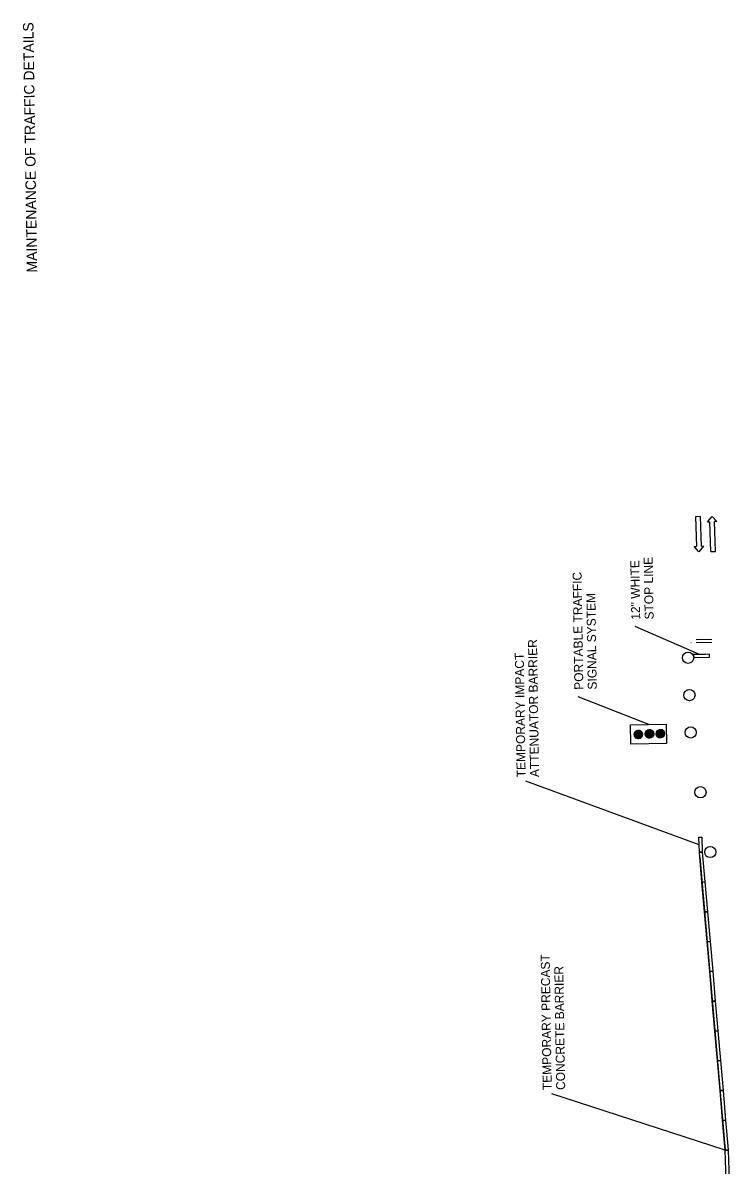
# Model space of a CAD drawing. Extents: x 1770269 to 1771406, y 724066 to 730989.
# Drawn here: x 1770350 to 1770823, y 724837 to 725601 of the extents above; entities that cross this region are included whole.
import ezdxf

# ---------------------------------------------------------------- set-up
doc = ezdxf.new("R2010")
doc.units = 0
for name, color, linetype in [('Default', 7, 'Continuous'), ('R_Border', 7, 'Continuous'), ('R_Border Notes', 7, 'Continuous'), ('R_Dimension', 7, 'Continuous'), ('R_MOT', 7, 'Continuous'), ('R_Striping', 7, 'Continuous'), ('T_Vehicle Path Rt', 7, 'Continuous')]:
    doc.layers.add(name, color=color, linetype=linetype)

msp = doc.modelspace()

# ---------------------------------------------------------------- linework, layer by layer
at = {"layer": 'Default'}
for p, q in [((1770797.34, 725186.19), (1770797.5, 725186.19)), ((1770762.37, 725121.93), (1770759.32, 725124.89)), ((1770762.19, 725121.92), (1770759.32, 725124.71)), ((1770762.53, 725121.94), (1770759.33, 725125.05)), ((1770762.01, 725121.93), (1770759.33, 725124.53)), ((1770762.69, 725121.97), (1770759.34, 725125.21)), ((1770761.81, 725121.95), (1770759.35, 725124.33)), ((1770762.84, 725122), (1770759.37, 725125.36)), ((1770762.98, 725122.03), (1770759.4, 725125.5)), ((1770761.59, 725121.99), (1770759.4, 725124.11)), ((1770763.11, 725122.08), (1770759.44, 725125.64)), ((1770761.34, 725122.05), (1770759.47, 725123.87)), ((1770763.24, 725122.12), (1770759.48, 725125.77)), ((1770763.37, 725122.18), (1770759.53, 725125.9)), ((1770763.49, 725122.23), (1770759.59, 725126.02)), ((1770761.05, 725122.16), (1770759.59, 725123.58)), ((1770763.61, 725122.3), (1770759.65, 725126.14)), ((1770763.72, 725122.36), (1770759.71, 725126.25)), ((1770763.82, 725122.43), (1770759.78, 725126.36)), ((1770760.66, 725122.36), (1770759.8, 725123.2)), ((1770763.93, 725122.51), (1770759.85, 725126.46)), ((1770764.03, 725122.59), (1770759.92, 725126.56)), ((1770764.12, 725122.67), (1770760, 725126.66)), ((1770764.21, 725122.75), (1770760.08, 725126.76)), ((1770764.3, 725122.84), (1770760.17, 725126.85)), ((1770764.38, 725122.94), (1770760.26, 725126.93)), ((1770764.46, 725123.03), (1770760.36, 725127.01)), ((1770764.54, 725123.14), (1770760.46, 725127.09)), ((1770764.61, 725123.24), (1770760.56, 725127.17)), ((1770764.67, 725123.35), (1770760.67, 725127.24)), ((1770764.74, 725123.46), (1770760.78, 725127.3)), ((1770764.79, 725123.58), (1770760.89, 725127.36)), ((1770764.85, 725123.7), (1770761.01, 725127.42)), ((1770764.9, 725123.83), (1770761.14, 725127.47)), ((1770764.94, 725123.96), (1770761.27, 725127.52)), ((1770764.98, 725124.1), (1770761.4, 725127.56)), ((1770765.01, 725124.24), (1770761.55, 725127.6)), ((1770765.04, 725124.39), (1770761.69, 725127.63)), ((1770765.05, 725124.55), (1770761.85, 725127.65)), ((1770765.06, 725124.71), (1770762.02, 725127.67)), ((1770765.06, 725124.89), (1770762.19, 725127.67)), ((1770765.05, 725125.07), (1770762.37, 725127.67)), ((1770765.03, 725125.27), (1770762.58, 725127.65)), ((1770764.98, 725125.49), (1770762.79, 725127.61)), ((1770764.91, 725125.73), (1770763.04, 725127.55)), ((1770764.79, 725126.02), (1770763.33, 725127.44)), ((1770764.57, 725126.41), (1770763.72, 725127.23)), ((1770769.85, 725122.31), (1770766.8, 725125.27)), ((1770769.67, 725122.3), (1770766.8, 725125.09)), ((1770770.01, 725122.32), (1770766.81, 725125.43)), ((1770769.49, 725122.31), (1770766.81, 725124.91)), ((1770770.17, 725122.35), (1770766.83, 725125.59)), ((1770769.29, 725122.33), (1770766.83, 725124.71)), ((1770770.32, 725122.38), (1770766.85, 725125.74)), ((1770770.46, 725122.41), (1770766.88, 725125.88)), ((1770769.07, 725122.37), (1770766.88, 725124.49)), ((1770770.59, 725122.45), (1770766.92, 725126.02)), ((1770768.82, 725122.43), (1770766.95, 725124.25)), ((1770770.72, 725122.5), (1770766.96, 725126.15)), ((1770770.85, 725122.56), (1770767.01, 725126.27)), ((1770770.97, 725122.61), (1770767.07, 725126.4)), ((1770768.53, 725122.54), (1770767.07, 725123.96)), ((1770771.09, 725122.67), (1770767.13, 725126.51)), ((1770771.2, 725122.74), (1770767.19, 725126.63)), ((1770771.3, 725122.81), (1770767.26, 725126.74)), ((1770768.14, 725122.74), (1770767.28, 725123.57)), ((1770771.41, 725122.89), (1770767.33, 725126.84)), ((1770771.51, 725122.96), (1770767.4, 725126.94)), ((1770771.6, 725123.05), (1770767.48, 725127.04)), ((1770771.69, 725123.13), (1770767.56, 725127.13)), ((1770771.78, 725123.22), (1770767.65, 725127.22)), ((1770771.86, 725123.32), (1770767.74, 725127.31)), ((1770771.94, 725123.41), (1770767.84, 725127.39)), ((1770772.02, 725123.51), (1770767.94, 725127.47)), ((1770772.09, 725123.62), (1770768.04, 725127.54)), ((1770772.15, 725123.73), (1770768.15, 725127.61)), ((1770772.22, 725123.84), (1770768.26, 725127.68)), ((1770772.27, 725123.96), (1770768.37, 725127.74)), ((1770772.33, 725124.08), (1770768.49, 725127.8)), ((1770772.38, 725124.21), (1770768.62, 725127.85)), ((1770772.42, 725124.34), (1770768.75, 725127.9)), ((1770772.46, 725124.48), (1770768.88, 725127.94)), ((1770772.49, 725124.62), (1770769.03, 725127.98)), ((1770772.52, 725124.77), (1770769.18, 725128.01)), ((1770772.53, 725124.93), (1770769.33, 725128.03)), ((1770772.54, 725125.09), (1770769.5, 725128.05)), ((1770772.54, 725125.26), (1770769.67, 725128.05)), ((1770772.53, 725125.45), (1770769.86, 725128.05)), ((1770772.51, 725125.65), (1770770.06, 725128.03)), ((1770772.46, 725125.87), (1770770.27, 725127.99)), ((1770772.39, 725126.11), (1770770.52, 725127.92)), ((1770772.27, 725126.4), (1770770.81, 725127.82)), ((1770772.05, 725126.78), (1770771.2, 725127.61)), ((1770777.02, 725122.42), (1770774.06, 725125.28)), ((1770777.19, 725122.43), (1770774.07, 725125.45)), ((1770776.84, 725122.42), (1770774.07, 725125.1)), ((1770777.35, 725122.44), (1770774.08, 725125.61)), ((1770776.65, 725122.43), (1770774.09, 725124.91)), ((1770777.5, 725122.47), (1770774.1, 725125.77)), ((1770777.65, 725122.5), (1770774.13, 725125.91)), ((1770776.44, 725122.46), (1770774.13, 725124.7)), ((1770777.79, 725122.54), (1770774.17, 725126.05)), ((1770776.21, 725122.51), (1770774.18, 725124.47)), ((1770777.92, 725122.59), (1770774.21, 725126.19)), ((1770778.05, 725122.64), (1770774.25, 725126.32)), ((1770775.94, 725122.59), (1770774.28, 725124.21)), ((1770778.17, 725122.69), (1770774.31, 725126.44)), ((1770778.29, 725122.75), (1770774.36, 725126.56)), ((1770778.4, 725122.82), (1770774.42, 725126.68)), ((1770775.61, 725122.74), (1770774.43, 725123.88)), ((1770778.51, 725122.88), (1770774.49, 725126.79)), ((1770778.62, 725122.96), (1770774.56, 725126.9)), ((1770778.72, 725123.03), (1770774.63, 725127)), ((1770778.82, 725123.11), (1770774.71, 725127.1)), ((1770778.91, 725123.2), (1770774.79, 725127.19)), ((1770779, 725123.28), (1770774.87, 725127.29)), ((1770779.08, 725123.37), (1770774.96, 725127.37)), ((1770779.17, 725123.47), (1770775.05, 725127.46)), ((1770779.24, 725123.57), (1770775.15, 725127.54)), ((1770779.32, 725123.67), (1770775.25, 725127.62)), ((1770779.39, 725123.78), (1770775.35, 725127.69)), ((1770779.45, 725123.89), (1770775.46, 725127.76)), ((1770779.51, 725124.01), (1770775.58, 725127.82)), ((1770779.57, 725124.12), (1770775.69, 725127.88)), ((1770779.67, 725124.38), (1770775.94, 725127.99)), ((1770779.71, 725124.51), (1770776.08, 725128.03)), ((1770779.74, 725124.65), (1770776.22, 725128.07)), ((1770779.77, 725124.8), (1770776.36, 725128.11)), ((1770779.79, 725124.95), (1770776.51, 725128.13)), ((1770779.81, 725125.11), (1770776.67, 725128.15)), ((1770779.81, 725125.28), (1770776.84, 725128.16)), ((1770779.81, 725125.46), (1770777.02, 725128.16)), ((1770779.79, 725125.65), (1770777.21, 725128.15)), ((1770779.76, 725125.86), (1770777.42, 725128.12)), ((1770779.7, 725126.08), (1770777.65, 725128.08)), ((1770779.61, 725126.34), (1770777.91, 725128)), ((1770779.47, 725126.66), (1770778.23, 725127.86)), ((1770779.07, 725127.21), (1770778.8, 725127.48))]:
    msp.add_line(p, q, dxfattribs=at)
msp.add_lwpolyline([(1770757.06, 725118.29), (1770756.86, 725131.28), (1770780.83, 725131.65), (1770781.03, 725118.66)], close=True, dxfattribs=at)
for centre in [(1770762.19, 725124.8), (1770769.67, 725125.18), (1770776.94, 725125.29)]:
    msp.add_circle(centre, 2.87, dxfattribs=at)
at = {"layer": 'R_Border Notes'}
for p, q in [((1770803.62, 725270.55), (1770800.43, 725270.45)), ((1770800.43, 725270.45), (1770801.06, 725250.47)), ((1770803.62, 725270.55), (1770804.26, 725250.58)), ((1770808.43, 725267.03), (1770811.52, 725270.64)), ((1770808.43, 725267.03), (1770810.03, 725267.08)), ((1770810.67, 725247.1), (1770810.03, 725267.08)), ((1770811.52, 725270.64), (1770814.83, 725267.23)), ((1770814.83, 725267.23), (1770813.23, 725267.18)), ((1770813.87, 725247.21), (1770813.23, 725267.18)), ((1770799.47, 725250.42), (1770801.06, 725250.47)), ((1770802.78, 725247.02), (1770799.47, 725250.42)), ((1770805.86, 725250.63), (1770802.78, 725247.02)), ((1770805.86, 725250.63), (1770804.26, 725250.58)), ((1770810.67, 725247.1), (1770813.87, 725247.21))]:
    msp.add_line(p, q, dxfattribs=at)
at = {"layer": 'R_Dimension'}
for p, q in [((1770803.22, 725178.28), (1770760, 725196.92)), ((1770769.16, 725131.47), (1770721.94, 725150.05)), ((1770802.88, 725051), (1770686.84, 725093.61))]:
    msp.add_line(p, q, dxfattribs=at)
msp.add_lwpolyline([(1770820.35, 724846.64), (1770704.29, 724884.34)], dxfattribs=at)
at = {"layer": 'R_MOT'}
for centre in [(1770795.53, 725176.06), (1770796.38, 725151.08), (1770797.23, 725126.09), (1770803.79, 725086.1), (1770810.35, 725046.11)]:
    msp.add_circle(centre, 3.75, dxfattribs=at)
at = {"layer": 'R_Striping'}
for p, q in [((1770800.95, 725188.25), (1770811.3, 725188.41)), ((1770800.97, 725186.25), (1770811.34, 725186.41)), ((1770799.21, 725178.22), (1770799.26, 725176.49)), ((1770799.26, 725176.49), (1770799.26, 725176.48)), ((1770799.28, 725176.22), (1770809.79, 725176.38)), ((1770809.79, 725176.38), (1770809.75, 725178.38))]:
    msp.add_line(p, q, dxfattribs=at)
msp.add_lwpolyline([(1770809.75, 725178.38), (1770807.23, 725178.34), (1770799.21, 725178.22)], dxfattribs=at)
for start, end in [(2.93525, 6.53038), (2.55633, 2.74579), (2.55633, 2.74579)]:
    msp.add_arc((1770795.53, 725176.06), 3.75, start, end, dxfattribs=at)
at = {"layer": 'T_Vehicle Path Rt'}
msp.add_line((1770803.28, 725042.94), (1770820.35, 724846.64), dxfattribs=at)
for points in [[(1770803.02, 725046), (1770802.74, 725056), (1770804.74, 725056.05), (1770805.02, 725046.06)], [(1770804.76, 725025.96), (1770803.03, 725045.88), (1770805.02, 725046.06), (1770806.75, 725026.13)], [(1770806.49, 725006.03), (1770804.76, 725025.96), (1770806.75, 725026.13), (1770808.48, 725006.21)], [(1770808.22, 724986.11), (1770806.49, 725006.03), (1770808.48, 725006.21), (1770810.22, 724986.28)], [(1770809.96, 724966.19), (1770808.22, 724986.11), (1770810.22, 724986.28), (1770811.95, 724966.36)], [(1770811.69, 724946.26), (1770809.96, 724966.19), (1770811.95, 724966.36), (1770813.68, 724946.43)], [(1770813.42, 724926.34), (1770811.69, 724946.26), (1770813.68, 724946.43), (1770815.41, 724926.51)], [(1770815.15, 724906.41), (1770813.42, 724926.34), (1770815.41, 724926.51), (1770817.15, 724906.58)], [(1770816.89, 724886.49), (1770815.15, 724906.41), (1770817.15, 724906.58), (1770818.88, 724886.66)], [(1770818.62, 724866.56), (1770816.89, 724886.49), (1770818.88, 724886.66), (1770820.61, 724866.74)], [(1770820.35, 724846.64), (1770818.62, 724866.56), (1770820.61, 724866.74), (1770822.34, 724846.81)], [(1770820.99, 724826.65), (1770820.35, 724846.64), (1770822.35, 724846.7), (1770822.99, 724826.71)]]:
    msp.add_lwpolyline(points, close=True, dxfattribs=at)

# ---------------------------------------------------------------- texts
at = {"layer": 'R_Border'}
msp.add_text('MAINTENANCE OF TRAFFIC DETAILS', height=7, rotation=90.88269, dxfattribs=at).set_placement((1770359.81, 725433.81))
at = {"layer": 'R_Dimension'}
for s, p in [('12" WHITE', (1770763.44, 725201.57)), ('STOP LINE', (1770772.44, 725201.71)), ('PORTABLE TRAFFIC', (1770725.38, 725154.7)), ('SIGNAL SYSTEM', (1770734.37, 725154.84)), ('ATTENUATOR BARRIER', (1770695.75, 725096.28)), ('TEMPORARY IMPACT', (1770686.75, 725096.15)), ('TEMPORARY PRECAST', (1770704.21, 724886.88)), ('CONCRETE BARRIER', (1770713.21, 724887.01))]:
    msp.add_text(s, height=6, rotation=90.88269, dxfattribs=at).set_placement(p)

doc.saveas('drawing.dxf')
